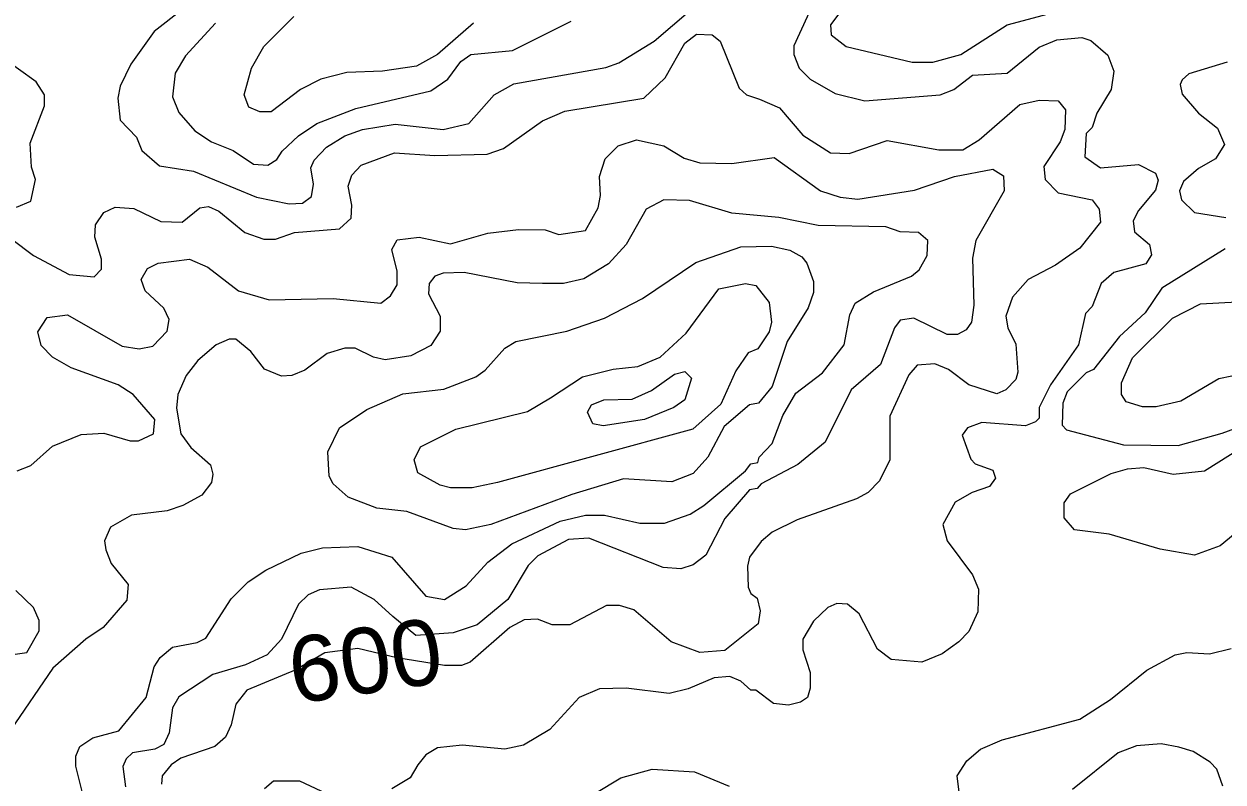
# Model space of a CAD drawing. Extents: x 577 to 602.9, y 7483.8 to 7511.6.
# Drawn here: x 589.958 to 591.419, y 7495.147 to 7496.07 of the extents above; entities that cross this region are included whole.
import ezdxf
from ezdxf.enums import TextEntityAlignment as Align

# ---------------------------------------------------------------- set-up
doc = ezdxf.new("R2010")
doc.units = 0
doc.header["$LTSCALE"] = 0.032
doc.layers.add('1', color=7, linetype='Continuous', lineweight=25)
doc.layers.add('2', color=7, linetype='Continuous', lineweight=13)
doc.layers.add('61', color=7, linetype='Continuous')

msp = doc.modelspace()

# ---------------------------------------------------------------- linework, layer by layer
at = {"layer": '1'}
for points in [[(589.9433, 7495.8084), (589.9696, 7495.7885), (590.0133, 7495.7655), (590.0435, 7495.7623), (590.0523, 7495.7718), (590.0523, 7495.7838), (590.0443, 7495.8108), (590.0451, 7495.8259), (590.0555, 7495.841), (590.069, 7495.8474), (590.092, 7495.8458), (590.1246, 7495.8299), (590.1509, 7495.8291), (590.1723, 7495.8466), (590.1827, 7495.8482), (590.1954, 7495.8426), (590.2272, 7495.8164), (590.2503, 7495.8084), (590.2646, 7495.8084), (590.2876, 7495.8164), (590.3425, 7495.8211), (590.3568, 7495.8338), (590.3576, 7495.8497), (590.3529, 7495.8728), (590.3576, 7495.8863), (590.3688, 7495.8983), (590.4093, 7495.9134), (590.4586, 7495.9102), (590.5222, 7495.9118), (590.5421, 7495.9189), (590.5898, 7495.9523), (590.6168, 7495.9643), (590.7131, 7495.9802), (590.7393, 7496.0048), (590.7632, 7496.047), (590.7775, 7496.0581), (590.7966, 7496.0573), (590.8061, 7496.0493), (590.8292, 7495.9921), (590.8382, 7495.984), (590.8543, 7495.9789), (590.8785, 7495.9682), (590.9071, 7495.9348), (590.9405, 7495.9134), (590.9635, 7495.9126), (591.0097, 7495.9285), (591.0725, 7495.9173), (591.1019, 7495.9173), (591.1218, 7495.9293), (591.1711, 7495.9722), (591.1949, 7495.9778), (591.218, 7495.977), (591.2267, 7495.9658), (591.226, 7495.942), (591.2204, 7495.9269), (591.2005, 7495.8967), (591.2021, 7495.8808), (591.218, 7495.8649), (591.2594, 7495.8561), (591.2681, 7495.845), (591.2697, 7495.8291), (591.2442, 7495.7973), (591.2148, 7495.7766), (591.1814, 7495.7591), (591.1623, 7495.7376), (591.1544, 7495.7146), (591.1568, 7495.7003), (591.1663, 7495.6804), (591.1687, 7495.6462)], [(591.1687, 7495.6462), (591.1663, 7495.6374), (591.1544, 7495.6247), (591.1433, 7495.6199), (591.1091, 7495.6311), (591.0844, 7495.6494), (591.0677, 7495.6565), (591.0462, 7495.6549), (591.0359, 7495.643), (591.0128, 7495.5929), (591.0128, 7495.5396), (591.0001, 7495.5142), (590.9866, 7495.4999), (590.9723, 7495.4919), (590.8999, 7495.4665), (590.8697, 7495.4514), (590.8562, 7495.4402), (590.8418, 7495.4212), (590.8395, 7495.41), (590.8403, 7495.3846), (590.8435, 7495.3767), (590.8513, 7495.371), (590.8548, 7495.3557), (590.8523, 7495.34), (590.8117, 7495.3074), (590.7815, 7495.3051), (590.7465, 7495.3178), (590.7011, 7495.3567), (590.6836, 7495.3623), (590.6677, 7495.3623), (590.6232, 7495.3385), (590.6017, 7495.3385), (590.5835, 7495.3456), (590.5675, 7495.3448), (590.5501, 7495.3353), (590.5015, 7495.2931), (590.4912, 7495.2892), (590.4705, 7495.2892), (590.4122, 7495.2984), (590.3647, 7495.3098), (590.3245, 7495.3046), (590.2894, 7495.284), (590.2296, 7495.2589), (590.2161, 7495.2422), (590.2105, 7495.2168), (590.2034, 7495.2017), (590.1906, 7495.1905), (590.1493, 7495.1762), (590.1374, 7495.1683), (590.1262, 7495.1548), (590.1254, 7495.1444)]]:
    msp.add_lwpolyline(points, dxfattribs=at)
msp.add_lwpolyline([(590.6643, 7495.6128), (590.6988, 7495.6136), (590.7226, 7495.6239), (590.7504, 7495.6438), (590.7632, 7495.647), (590.7711, 7495.639), (590.7632, 7495.6128), (590.7496, 7495.6032), (590.7139, 7495.5889), (590.6638, 7495.581), (590.651, 7495.5834), (590.6447, 7495.5977), (590.6495, 7495.6064)], close=True, dxfattribs=at)
at = {"layer": '2'}
for points in [[(590.1517, 7496.0883), (590.1167, 7496.0613), (590.0881, 7496.0215), (590.0753, 7495.9945), (590.0722, 7495.9802), (590.0753, 7495.9531), (590.0952, 7495.9324)], [(590.0952, 7495.9324), (590.1016, 7495.9165), (590.123, 7495.8975), (590.1644, 7495.8911), (590.2415, 7495.8593), (590.2813, 7495.8513), (590.2972, 7495.8521), (590.3083, 7495.8601), (590.3107, 7495.8752), (590.3075, 7495.8951), (590.3115, 7495.9046), (590.3266, 7495.9205), (590.3489, 7495.934), (590.3703, 7495.942), (590.4101, 7495.9484), (590.4689, 7495.942), (590.5, 7495.9491), (590.531, 7495.9841), (590.5548, 7495.9977), (590.6669, 7496.0175), (590.6828, 7496.0231), (590.7258, 7496.0493), (590.7703, 7496.0875)], [(590.9214, 7496.0994), (590.896, 7496.0438), (590.896, 7496.0334), (590.9023, 7496.0167), (590.9158, 7496.0032), (590.9461, 7495.9857), (590.9826, 7495.977), (591.0741, 7495.9841), (591.0908, 7495.9905), (591.1138, 7496.008), (591.156, 7496.0104), (591.1949, 7496.0422), (591.2164, 7496.0509), (591.2466, 7496.0541), (591.2578, 7496.0501), (591.2784, 7496.0326), (591.2856, 7496.0128), (591.2824, 7495.9905), (591.2649, 7495.9619), (591.2594, 7495.9444), (591.2522, 7495.9372), (591.2506, 7495.9086), (591.2697, 7495.8951), (591.3158, 7495.8991), (591.3365, 7495.8887), (591.3397, 7495.88), (591.3365, 7495.868), (591.3158, 7495.8434), (591.3094, 7495.8307), (591.311, 7495.8171), (591.3293, 7495.802), (591.3317, 7495.7893), (591.3246, 7495.7782), (591.2856, 7495.7678), (591.2705, 7495.7543), (591.2594, 7495.7265), (591.2514, 7495.7178), (591.2427, 7495.6796), (591.2085, 7495.6311), (591.1949, 7495.6032), (591.1949, 7495.5905), (591.1902, 7495.5858), (591.1782, 7495.581), (591.125, 7495.585), (591.1075, 7495.5786), (591.1011, 7495.5698), (591.1114, 7495.5404), (591.117, 7495.5349), (591.1385, 7495.5269), (591.1417, 7495.5174), (591.1345, 7495.507), (591.113, 7495.4999), (591.0924, 7495.4879), (591.0773, 7495.4609), (591.0828, 7495.441), (591.1138, 7495.3997), (591.121, 7495.3822), (591.1202, 7495.3544), (591.1091, 7495.3305), (591.0971, 7495.3178), (591.0765, 7495.3035), (591.0518, 7495.2931), (591.0144, 7495.2963), (590.9977, 7495.309), (590.9755, 7495.352)], [(590.9532, 7496.0859), (590.9405, 7496.0692), (590.9413, 7496.0573), (590.9596, 7496.043), (591.0399, 7496.0239), (591.0653, 7496.0239), (591.0995, 7496.0334), (591.156, 7496.0692), (591.2244, 7496.0875)], [(590.1914, 7496.0716), (590.1549, 7496.0318), (590.1421, 7496.0104), (590.1389, 7495.9817), (590.1469, 7495.9627), (590.166, 7495.9404), (590.1867, 7495.9269), (590.2129, 7495.9165), (590.2376, 7495.8998), (590.255, 7495.8983), (590.2662, 7495.9054), (590.2725, 7495.9157), (590.2924, 7495.934), (590.3147, 7495.9491), (590.3624, 7495.9674), (590.4538, 7495.9889), (590.4745, 7496.0032), (590.4904, 7496.0247), (590.5023, 7496.0334), (590.5532, 7496.0382), (590.6248, 7496.074)], [(590.5055, 7496.0716), (590.4618, 7496.0334), (590.4363, 7496.0191), (590.395, 7496.0128), (590.3513, 7496.0112), (590.3195, 7496.0032), (590.2948, 7495.9905), (590.259, 7495.9635), (590.2455, 7495.9635), (590.232, 7495.969), (590.2264, 7495.9841), (590.2352, 7496.0167), (590.2503, 7496.043), (590.2869, 7496.0796)], [(589.9489, 7495.8474), (589.9664, 7495.8545), (589.972, 7495.8808), (589.9672, 7495.8959), (589.9656, 7495.9253), (589.9831, 7495.9706), (589.9831, 7495.9841), (589.9728, 7496), (589.9298, 7496.031)], [(591.424, 7496.0239), (591.377, 7496.0096), (591.3691, 7496.0024), (591.3667, 7495.9969), (591.3691, 7495.9849), (591.389, 7495.9619), (591.412, 7495.9436), (591.4208, 7495.9237), (591.4096, 7495.9062), (591.389, 7495.8943), (591.3707, 7495.8784), (591.3659, 7495.8672), (591.3683, 7495.8561), (591.3842, 7495.841), (591.4224, 7495.8346)], [(590.6606, 7495.8617), (590.659, 7495.8847), (590.6662, 7495.9062), (590.6821, 7495.9221), (590.7043, 7495.9293), (590.7377, 7495.9221), (590.7624, 7495.907), (590.7815, 7495.9014), (590.8204, 7495.9006), (590.8721, 7495.9078), (590.9286, 7495.8672), (590.9524, 7495.8593), (590.9739, 7495.8569), (591.0431, 7495.868), (591.0916, 7495.8847), (591.1385, 7495.8935), (591.1512, 7495.8855), (591.152, 7495.8672), (591.1178, 7495.8068), (591.1138, 7495.7853), (591.1154, 7495.7281), (591.1122, 7495.7074), (591.1059, 7495.6979), (591.0955, 7495.6923), (591.0828, 7495.6923), (591.0423, 7495.7122), (591.0256, 7495.7098), (591.0184, 7495.7003), (591.0017, 7495.6557), (590.9659, 7495.6247), (590.9341, 7495.5611), (590.9007, 7495.5341), (590.8562, 7495.5102), (590.8514, 7495.5046), (590.8419, 7495.5031), (590.8117, 7495.4681), (590.7886, 7495.4235), (590.7735, 7495.4116), (590.7584, 7495.4068), (590.7369, 7495.4084), (590.6463, 7495.4442), (590.6216, 7495.4426), (590.5842, 7495.4227), (590.5723, 7495.4108), (590.5477, 7495.3695), (590.5103, 7495.3385), (590.4809, 7495.3289), (590.4355, 7495.3257), (590.4074, 7495.3486)], [(591.0081, 7495.8235), (590.9254, 7495.8251), (590.8777, 7495.8346), (590.8204, 7495.8402), (590.7687, 7495.8553), (590.7377, 7495.8561), (590.7162, 7495.845), (590.6916, 7495.802), (590.6701, 7495.7782), (590.6399, 7495.7599), (590.6153, 7495.7543), (590.5898, 7495.7543), (590.5588, 7495.7551), (590.4944, 7495.7678), (590.4689, 7495.7671), (590.4586, 7495.7631), (590.4515, 7495.7543), (590.4507, 7495.7416), (590.465, 7495.7146), (590.465, 7495.6963), (590.4538, 7495.6788), (590.4292, 7495.6661), (590.3982, 7495.6613), (590.3839, 7495.6645), (590.3616, 7495.6756), (590.3489, 7495.6756), (590.3274, 7495.6692), (590.3004, 7495.6486), (590.2845, 7495.6422), (590.2717, 7495.6414), (590.2511, 7495.6502), (590.2344, 7495.6716), (590.2161, 7495.6867), (590.2081, 7495.6867), (590.1922, 7495.6796), (590.17, 7495.6605), (590.1556, 7495.6422), (590.1453, 7495.6191), (590.1437, 7495.6025), (590.1493, 7495.5714), (590.1612, 7495.5547), (590.1851, 7495.5333), (590.1882, 7495.5221), (590.1867, 7495.5118), (590.1747, 7495.4967), (590.1517, 7495.484), (590.1326, 7495.4776), (590.0889, 7495.472), (590.0634, 7495.4577), (590.0563, 7495.441), (590.0578, 7495.4299), (590.0642, 7495.4132), (590.0849, 7495.3878), (590.0833, 7495.3687), (590.0547, 7495.3353), (590.0332, 7495.321), (589.9934, 7495.286), (589.9417, 7495.2104)], [(589.9497, 7495.5261), (589.9664, 7495.5325), (589.9926, 7495.5563), (590.0276, 7495.5706), (590.0555, 7495.5722), (590.0873, 7495.5627), (590.0976, 7495.5627), (590.1159, 7495.5714), (590.1175, 7495.5889), (590.0912, 7495.6191), (590.0729, 7495.6311), (590.0157, 7495.6518), (589.9926, 7495.6645), (589.9791, 7495.6788), (589.9751, 7495.6955), (589.9863, 7495.713), (590.0109, 7495.7162), (590.0777, 7495.678), (590.0984, 7495.6748), (590.1151, 7495.678), (590.1326, 7495.6963), (590.135, 7495.7106), (590.1286, 7495.7241), (590.1056, 7495.7456), (590.1008, 7495.7591), (590.1087, 7495.7726), (590.1215, 7495.779), (590.1596, 7495.7838), (590.1819, 7495.7742), (590.2193, 7495.7456), (590.2566, 7495.7344), (590.3346, 7495.736), (590.3926, 7495.7305), (590.4045, 7495.7392), (590.4125, 7495.7527), (590.4125, 7495.7694), (590.4061, 7495.7957), (590.4125, 7495.8076), (590.4395, 7495.8108), (590.4777, 7495.8028), (590.523, 7495.8156), (590.5604, 7495.8203), (590.593, 7495.8195), (590.6097, 7495.814), (590.6423, 7495.8187), (590.6574, 7495.8466), (590.6606, 7495.8617)], [(590.0308, 7495.1277), (590.0213, 7495.1667), (590.0213, 7495.1786), (590.026, 7495.1905), (590.0419, 7495.2009), (590.0737, 7495.2096), (590.1071, 7495.2502), (590.1167, 7495.2876), (590.1238, 7495.2987), (590.1389, 7495.3114), (590.1692, 7495.317), (590.1795, 7495.3225), (590.2105, 7495.3703), (590.2312, 7495.3909), (590.2527, 7495.4052), (590.2956, 7495.4259), (590.3218, 7495.4323), (590.3648, 7495.4339), (590.4061, 7495.4211), (590.4475, 7495.3734), (590.4705, 7495.3695), (590.4968, 7495.3862), (590.523, 7495.4148), (590.5524, 7495.4371), (590.6113, 7495.4649), (590.6423, 7495.472), (590.6654, 7495.472), (590.7083, 7495.4625), (590.7385, 7495.4625), (590.7695, 7495.4736), (590.7862, 7495.484), (590.8371, 7495.5261), (590.8435, 7495.5349), (590.8522, 7495.5365), (590.8538, 7495.5428), (590.8697, 7495.5595), (590.8824, 7495.5937), (590.8983, 7495.6207), (590.9309, 7495.6454), (590.9572, 7495.6796), (590.9643, 7495.7162), (590.9707, 7495.7305), (590.993, 7495.744), (591.0391, 7495.7631), (591.0486, 7495.771), (591.0582, 7495.7885), (591.059, 7495.8068), (591.0478, 7495.8164), (591.0256, 7495.8171), (591.0081, 7495.8235)], [(591.4216, 7495.7965), (591.3444, 7495.7488), (591.3238, 7495.7185), (591.2927, 7495.6899), (591.2609, 7495.6494), (591.2522, 7495.6454), (591.2291, 7495.6223), (591.2236, 7495.6088), (591.2228, 7495.5818), (591.2283, 7495.5762), (591.2975, 7495.5579), (591.3643, 7495.5571), (591.4176, 7495.5722), (591.4939, 7495.6001)], [(591.4295, 7495.6414), (591.4136, 7495.6382), (591.3675, 7495.6112), (591.3373, 7495.604), (591.3206, 7495.604), (591.3007, 7495.6104), (591.2951, 7495.6191), (591.2951, 7495.6335), (591.3087, 7495.6637), (591.3572, 7495.7122), (591.3914, 7495.7297), (591.4359, 7495.7321)], [(591.4518, 7495.4649), (591.4152, 7495.4347), (591.3842, 7495.4235), (591.3421, 7495.4307), (591.28, 7495.449), (591.2379, 7495.4545), (591.2252, 7495.4689), (591.2252, 7495.4871), (591.2331, 7495.4983), (591.2442, 7495.5038), (591.2824, 7495.5229), (591.3023, 7495.5285), (591.3222, 7495.5301), (591.358, 7495.5221), (591.3961, 7495.5261), (591.4597, 7495.5659)], [(589.9306, 7495.3003), (589.9616, 7495.3051), (589.9767, 7495.3313), (589.9767, 7495.344), (589.9696, 7495.3599), (589.9481, 7495.3806)], [(590.4074, 7495.3486), (590.3847, 7495.3695), (590.3568, 7495.3846), (590.3179, 7495.3814), (590.3043, 7495.375), (590.2924, 7495.3639), (590.2717, 7495.321), (590.2542, 7495.3019), (590.228, 7495.2899), (590.1882, 7495.278), (590.1469, 7495.251), (590.1389, 7495.2375), (590.135, 7495.2072), (590.1286, 7495.1929), (590.1175, 7495.1874), (590.0904, 7495.1826), (590.0825, 7495.1754), (590.0785, 7495.1659), (590.0817, 7495.1412)], [(590.9755, 7495.352), (590.9612, 7495.3639), (590.9484, 7495.3647), (590.9373, 7495.3599), (590.9198, 7495.3432), (590.9071, 7495.321), (590.9071, 7495.3082), (590.9158, 7495.2804), (590.9158, 7495.2613), (590.9127, 7495.2502), (590.9039, 7495.2446), (590.8896, 7495.2406), (590.8713, 7495.243), (590.8498, 7495.2589), (590.8435, 7495.2589), (590.8315, 7495.2701), (590.818, 7495.2756), (590.7989, 7495.274), (590.7671, 7495.2605), (590.7441, 7495.255), (590.6916, 7495.2613), (590.659, 7495.2605), (590.6343, 7495.2502), (590.5986, 7495.2112), (590.5668, 7495.1921), (590.5437, 7495.1874), (590.492, 7495.1921), (590.4618, 7495.189), (590.4475, 7495.1802), (590.4379, 7495.1683), (590.4284, 7495.1524), (590.4061, 7495.1389)], [(591.0979, 7495.1317), (591.0948, 7495.1548), (591.1067, 7495.1731), (591.1234, 7495.1874), (591.1496, 7495.1985), (591.2442, 7495.2239), (591.2816, 7495.2478), (591.3261, 7495.2836), (591.3603, 7495.3019), (591.3747, 7495.3051), (591.4025, 7495.3035), (591.4287, 7495.3098)], [(591.4184, 7495.142), (591.4112, 7495.1627), (591.4033, 7495.1715), (591.3826, 7495.1842), (591.3651, 7495.1898), (591.3436, 7495.1937), (591.3134, 7495.1913), (591.2912, 7495.1826), (591.2355, 7495.1381)], [(590.6534, 7495.1333), (590.6852, 7495.1524), (590.7234, 7495.1627), (590.7751, 7495.1595), (590.8172, 7495.142)], [(590.3401, 7495.1269), (590.294, 7495.1484), (590.2622, 7495.1484), (590.2511, 7495.1389)]]:
    msp.add_lwpolyline(points, dxfattribs=at)
for points in [[(590.5087, 7495.6406), (590.5198, 7495.6486), (590.5437, 7495.6756), (590.5572, 7495.6836), (590.6192, 7495.6963), (590.6654, 7495.7122), (590.7115, 7495.736), (590.7767, 7495.7798), (590.8315, 7495.7989), (590.8689, 7495.7997), (590.8912, 7495.7949), (590.9055, 7495.7869), (590.9119, 7495.779), (590.9198, 7495.7567), (590.9198, 7495.7432), (590.9135, 7495.7249), (590.888, 7495.6836), (590.8697, 7495.6287), (590.853, 7495.6088), (590.8419, 7495.6064), (590.8109, 7495.5802), (590.791, 7495.5428), (590.7735, 7495.5229), (590.7473, 7495.5126), (590.6884, 7495.5166), (590.6256, 7495.4975), (590.527, 7495.4609), (590.496, 7495.4545), (590.4809, 7495.4561), (590.4244, 7495.4768), (590.3878, 7495.4808), (590.3529, 7495.4943), (590.3346, 7495.5102), (590.3298, 7495.5198), (590.3282, 7495.5492), (590.3425, 7495.5786), (590.3759, 7495.6009), (590.4196, 7495.6199), (590.4697, 7495.6255)], [(590.5994, 7495.6152), (590.6383, 7495.6406), (590.6757, 7495.6502), (590.7059, 7495.6533), (590.7329, 7495.6645), (590.7648, 7495.6939), (590.8045, 7495.748), (590.8371, 7495.7543), (590.8498, 7495.7519), (590.8657, 7495.7313), (590.8689, 7495.7074), (590.8657, 7495.6955), (590.8522, 7495.6748), (590.8403, 7495.67), (590.8252, 7495.6478), (590.8069, 7495.6072), (590.7727, 7495.577), (590.5349, 7495.5118), (590.5039, 7495.5054), (590.4777, 7495.5054), (590.465, 7495.5086), (590.4379, 7495.5237), (590.4332, 7495.5396), (590.4411, 7495.5555), (590.4841, 7495.577), (590.5715, 7495.5985)]]:
    msp.add_lwpolyline(points, close=True, dxfattribs=at)

# ---------------------------------------------------------------- texts
at = {"layer": '61', "width": 1.05}
msp.add_text('600', height=0.08, rotation=8.254, dxfattribs=at).set_placement((590.3795, 7495.2556), align=Align.CENTER)

doc.saveas('drawing.dxf')
